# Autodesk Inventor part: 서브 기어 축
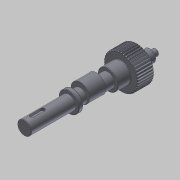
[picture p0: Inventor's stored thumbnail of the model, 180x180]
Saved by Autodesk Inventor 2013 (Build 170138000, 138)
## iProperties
Created: 2018-12
Part Number: 서브 기어 축
Material: 강철, 연강
Document SubType Name: Modeling
Designer: mduedu
Categories: <?xml version="1.0" encoding="UTF-16"?> <MemberInstance><Categories><FamilyTemplate><FamilyTemplateParameter ValueType="xs:double" Id="1" ObjectReferenceKey="da
Density: 7.86 g/cm^3
Mass: 514.749 g
Surface Area: 160.366 cm^2
Volume: 65.4897 cm^3
Author: mduedu
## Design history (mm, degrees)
sketch "Sketch1"
  geometry: C1 r 21.3 at (0, 0)
  constraints: 1 centre point
  dimensions: "d0" = 42.6 diameter of C1 (= da_da)
extrude "Extrusion1" new body sketch "Sketch1" distance "d1" = 20 (= da_b); taper "d2" = 0 deg
workplane "Work Plane2"
sketch "Sketch2"
  geometry: C1 r 21.3 at (0, 0) reference; C2 r 20.5 at (0, 0)
  constraints: 1 centre point, 1 coincident
  dimensions: "d3" = 41 diameter of C2 (= da_dw)
feature "피치 지름" sketch "Sketch2" dims "d4" = 10, "d5" = 0
workplane "Work Plane8"
workplane "Work Plane9"
chamfer "모따기1" distance "d49" = 1; stored, may be unused: second distance "d50" = 2, angle "d51" = 45 deg
sketch "스케치3"
  geometry: C1 r 12.5 at (0, 0); 1 further point
  constraints: 1 centre point, 1 coincident
  dimensions: "d52" = 25 diameter of C1
extrude "돌출2" join sketch "스케치3" distance "d53" = 16; taper "d54" = 0 deg
sketch "스케치4"
  geometry: C1 r 8.5 at (0, 0); 1 further point
  constraints: 1 centre point, 1 coincident
  dimensions: "d55" = 17 diameter of C1
extrude "돌출3" join sketch "스케치4" distance "d56" = 103; taper "d57" = 0 deg
sketch "스케치5"
  geometry: C1 r 7.5 at (0, 0); 1 further point
  constraints: 1 centre point, 1 coincident
  dimensions: "d58" = 15 diameter of C1
extrude "돌출4" join sketch "스케치5" distance "d59" = 16; taper "d60" = 0 deg
sketch "스케치6"
  geometry: C1 r 4 at (0, 0); 1 further point
  constraints: 1 centre point, 1 coincident
  dimensions: "d61" = 8 diameter of C1
extrude "돌출5" join sketch "스케치6" distance "d62" = 7; taper "d63" = 0 deg
chamfer "모따기2" distance "d64" = 0.5; stored, may be unused: second distance "d65" = 2, angle "d66" = 45 deg
fillet "모깎기1" dims "d67" = 0.5
feature "스퍼 기어" dims "da_b" = 20, "da_d" = 41, "da_aw" = 31, "da_da" = 42.6, "da_df" = 39.086, "da_dw" = 41, angle "da_beta" = 0 deg, "da_lefttooth" = 0, "da_righttooth" = 0
node "작업 평면11"
sketch "스케치7"
  geometry: C1 r 11.5 at (0, 3); C2 r 8.5 at (0, 0) reference; 1 further point
  constraints: 1 centre point, 1 tangent, 1 vertical alignment
  dimensions: "d69" = 3 distance of point (0, 0) C1.centre; "d70" = 23 diameter of C1 (derived)
extrude "돌출6" join sketch "스케치7" stored distance "d71" = 20; taper "d72" = 0 deg
node "작업 평면12"
sketch "스케치8"
  geometry: C1 r 12.5 at (0, 0) reference; C2 r 12.5 at (0, 0) reference; 1 further point
extrude "돌출7" join sketch "스케치8" distance "d74" = 5; taper "d75" = 0 deg
chamfer "모따기3" distance "d76" = 0.5; stored, may be unused: second distance "d77" = 2, angle "d78" = 45 deg
sketch "스케치9"
  geometry: L1 (-8, 139)-(8, 139) reference; L2 (0, 139)-(0, 0); L3 (-8.5, 84)-(-8.5, 138.5) reference; L4 (-8.5, 115)-(0, 115); L5 (-8.5, 115)-(-8.5, 113.5); L6 (-8.5, 113.5)-(-7, 115); L7 (-7, 115)-(-8.5, 115)
  constraints: 10 end point, 4 point on line, 2 perpendicular, 1 collinear, 1 midpoint
  dimensions: "d79" = 24 distance between parallel lines of L4 L1; "d80" = 3 diameter of L5.end L4; "d81" = 45 deg angle of L6 L3
revolve "회전1" sketch "스케치9" stored, may be unused: angle "d82" = 90 deg
sketch "스케치10"
  geometry: L1 (-8.5, 116.5)-(-7, 115) reference; L2 (-8.5, 113.5)-(-7, 115) reference; 2 further points
  constraints: 1 coincident
node "작업점1"
node "작업 평면13"
sketch "스케치11"
  geometry: L1 (-2.5, 93.5)-(-2.5, 80.5); L2 (2.5, 80.5)-(2.5, 93.5); L3 (-8, 103)-(8, 103) reference; A1 r 2.5 centre (0, 93.5) between (2.5, 93.5) and (-2.5, 93.5); A2 r 2.5 centre (0, 80.5) between (-2.5, 80.5) and (2.5, 80.5); 1 further point
  constraints: 4 end point, 4 point on circle, 4 tangent, 2 centre point, 2 vertical alignment, 1 parallel
  dimensions: "d83" = 7 distance edge to line of A1 L3; "d84" = 18 dimension on A2 A1; "d85" = 5 distance between parallel lines of L1 L2
extrude "돌출8" cut sketch "스케치11" distance "d86" = 3; taper "d87" = 0 deg
sketch "스케치12" dims "d88" = 32
  geometry: C1 r 0.5 at (0, -16); 2 further points
  constraints: 2 vertical alignment, 1 centre point, 1 coincident, 2 other
  dimensions: "d89" = 1 diameter of C1
extrude "돌출9" join sketch "스케치12" distance "d90" = 0.3; taper "d91" = 0 deg
sketch "스케치13"
  geometry: C1 r 11.5 at (0, 3) reference; 1 further point
  node "절단 모서리 투영1"
body "Solid1"
body "Srf1"
node "투영된 루프1"
other parameters: "d16" = 31 (= da_aw), "d17" = 0, "d34" = 0.76624 (computed from da_z), "d39" = 0, "d41" = 0, "d43" = 31 (= da_aw), "d46" = 31 (= da_aw), "d47" = 0, "d48" = 0, "d68" = 24, "d73" = 48
